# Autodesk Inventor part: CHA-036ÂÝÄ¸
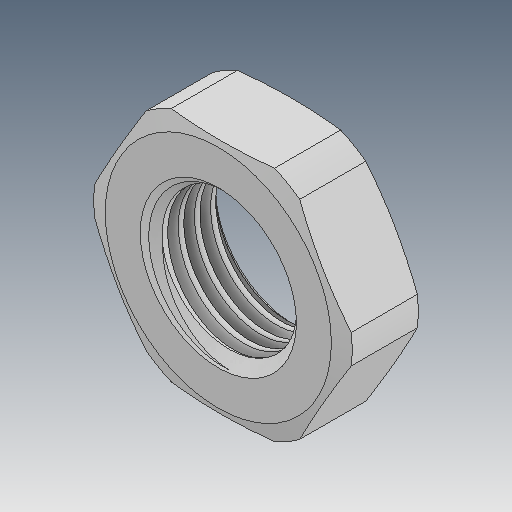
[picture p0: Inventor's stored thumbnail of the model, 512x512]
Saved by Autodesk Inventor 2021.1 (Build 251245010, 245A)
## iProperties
Created: 2019-12
Part Number: CHA-036ÂÝÄ¸
Material: Ogólny
Document SubType Name: Modeling
Designer: user
Density: 1 g/cm^3
Appearance: Domyślna
Author: user
Revision Number: ÈÎºÎ
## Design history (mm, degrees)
feature "ÊäÈë1"
node "Bryła1"
